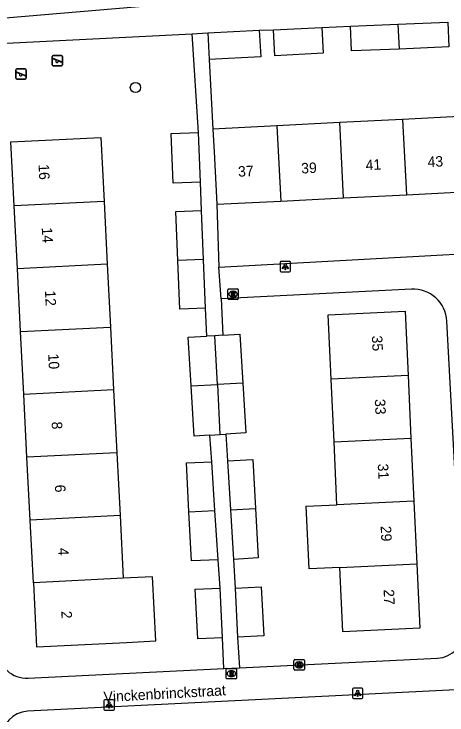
# Model space of a CAD drawing. Extents: x 160557 to 161245, y 385330 to 386505.
# Drawn here: x 160933.6 to 160974.9, y 385401.4 to 385468.3 of the extents above; entities that cross this region are included whole.
import ezdxf

# ---------------------------------------------------------------- set-up
doc = ezdxf.new("R2010")
doc.units = 0
for name, color, linetype in [('IMGEO_Boom', 7, 'Continuous'), ('IMGEO_Kolk', 7, 'Continuous'), ('IMGEO_Lichtpunt', 7, 'Continuous'), ('IMGEO_Openbare_ruimte_label', 7, 'Continuous'), ('IMGEO_Pand', 7, 'Continuous'), ('IMGEO_Pand_nummerreeks', 7, 'Continuous'), ('IMGEO_Rioolput', 7, 'Continuous'), ('IMGEO_Speelvoorziening', 7, 'Continuous'), ('IMGEO_Voetpad_open', 7, 'Continuous')]:
    doc.layers.add(name, color=color, linetype=linetype)

msp = doc.modelspace()

# ---------------------------------------------------------------- linework, layer by layer
at = {"layer": 'IMGEO_Boom'}
msp.add_circle((160945.22, 385461.28), 0.489, dxfattribs=at)
at = {"layer": 'IMGEO_Kolk'}
for p, q in [((160960.35, 385405.781), (160960.35, 385406.633)), ((160960.425, 385406.707), (160961.277, 385406.707)), ((160961.351, 385406.633), (160961.351, 385405.781)), ((160960.861, 385405.927), (160960.836, 385405.927)), ((160960.838, 385406.487), (160960.863, 385406.487)), ((160961.277, 385405.707), (160960.425, 385405.707))]:
    msp.add_line(p, q, dxfattribs=at)
for points in [[(160960.35, 385405.781), (160960.35, 385406.633)], [(160960.425, 385406.707), (160961.277, 385406.707)], [(160961.351, 385406.633), (160961.351, 385405.781)], [(160960.671, 385406.407), (160960.794, 385406.407), (160960.794, 385406.256), (160960.924, 385406.407), (160961.088, 385406.407), (160960.942, 385406.256), (160961.095, 385406.007), (160960.943, 385406.007), (160960.858, 385406.171), (160960.794, 385406.104), (160960.794, 385406.007), (160960.671, 385406.007), (160960.671, 385406.407)], [(160961.277, 385405.707), (160960.425, 385405.707)]]:
    msp.add_lwpolyline(points, dxfattribs=at)
for centre, start, end in [((160960.427, 385406.631), 91.55205, 178.44795), ((160960.427, 385406.631), 91.55205, 178.44795), ((160961.275, 385406.631), 1.55205, 88.44795), ((160961.275, 385406.631), 1.55205, 88.44795), ((160960.427, 385405.783), 181.55205, 268.44795), ((160960.427, 385405.783), 181.55205, 268.44795), ((160961.275, 385405.783), 271.55205, 358.44795), ((160961.275, 385405.783), 271.55205, 358.44795)]:
    msp.add_arc(centre, 0.0765, start, end, dxfattribs=at)
for centre, major_axis, ratio, start_param, end_param in [((160960.837, 385406.207), (-0.387, 0.002), 0.722429, 4.712389, 7.853982), ((160960.862, 385406.207), (-0.39, 0.002), 0.717154, 1.570796, 4.712389)]:
    msp.add_ellipse(centre, major_axis=major_axis, ratio=ratio, start_param=start_param, end_param=end_param, dxfattribs=at)
at = {"layer": 'IMGEO_Lichtpunt'}
for p, q in [((160959.925, 385444.698), (160959.117, 385444.698)), ((160959.925, 385444.698), (160959.117, 385444.698)), ((160959.023, 385444.603), (160959.023, 385443.796)), ((160959.023, 385444.603), (160959.023, 385443.796)), ((160960.019, 385443.796), (160960.019, 385444.603)), ((160960.019, 385443.796), (160960.019, 385444.603)), ((160959.117, 385443.702), (160959.925, 385443.702)), ((160959.117, 385443.702), (160959.925, 385443.702)), ((160965.922, 385403.892), (160965.922, 385403.085)), ((160965.922, 385403.892), (160965.922, 385403.085)), ((160966.824, 385403.987), (160966.016, 385403.987)), ((160966.824, 385403.987), (160966.016, 385403.987)), ((160966.918, 385403.085), (160966.918, 385403.892)), ((160966.918, 385403.085), (160966.918, 385403.892)), ((160942.224, 385402.782), (160942.224, 385401.975)), ((160942.224, 385402.782), (160942.224, 385401.975)), ((160943.126, 385402.877), (160942.318, 385402.877)), ((160943.126, 385402.877), (160942.318, 385402.877)), ((160943.22, 385401.975), (160943.22, 385402.782)), ((160943.22, 385401.975), (160943.22, 385402.782)), ((160966.016, 385402.991), (160966.824, 385402.991)), ((160966.016, 385402.991), (160966.824, 385402.991)), ((160942.318, 385401.881), (160943.126, 385401.881)), ((160942.318, 385401.881), (160943.126, 385401.881))]:
    msp.add_line(p, q, dxfattribs=at)
for points in [[(160959.397, 385444.267), (160959.436, 385444.239), (160959.248, 385443.977), (160959.21, 385444.004), (160959.397, 385444.267)], [(160959.499, 385444.219), (160959.546, 385444.219), (160959.546, 385443.897), (160959.499, 385443.897), (160959.499, 385444.219)], [(160959.609, 385444.239), (160959.647, 385444.266), (160959.834, 385444.004), (160959.795, 385443.976), (160959.609, 385444.239)], [(160966.296, 385403.556), (160966.335, 385403.528), (160966.147, 385403.266), (160966.109, 385403.293), (160966.296, 385403.556)], [(160966.398, 385403.508), (160966.445, 385403.508), (160966.445, 385403.186), (160966.398, 385403.186), (160966.398, 385403.508)], [(160966.508, 385403.528), (160966.546, 385403.555), (160966.733, 385403.293), (160966.694, 385403.265), (160966.508, 385403.528)], [(160942.598, 385402.446), (160942.637, 385402.418), (160942.449, 385402.156), (160942.411, 385402.183), (160942.598, 385402.446)], [(160942.7, 385402.398), (160942.747, 385402.398), (160942.747, 385402.076), (160942.7, 385402.076), (160942.7, 385402.398)], [(160942.81, 385402.418), (160942.848, 385402.445), (160943.035, 385402.183), (160942.996, 385402.155), (160942.81, 385402.418)]]:
    msp.add_lwpolyline(points, dxfattribs=at)
for centre in [(160959.522, 385444.401), (160966.421, 385403.69), (160942.723, 385402.58)]:
    msp.add_circle(centre, 0.0994, dxfattribs=at)
for centre, start, end in [((160959.117, 385444.603), 90, 180), ((160959.117, 385444.603), 90, 180), ((160959.925, 385444.603), 0, 90), ((160959.925, 385444.603), 0, 90), ((160959.117, 385443.796), 180, 270), ((160959.117, 385443.796), 180, 270), ((160959.925, 385443.796), 270, 0), ((160959.925, 385443.796), 270, 360), ((160966.016, 385403.892), 90, 180), ((160966.016, 385403.892), 90, 180), ((160966.824, 385403.892), 0, 90), ((160966.824, 385403.892), 0, 90), ((160942.318, 385402.782), 90, 180), ((160942.318, 385402.782), 90, 180), ((160943.126, 385402.782), 0, 90), ((160943.126, 385402.782), 0, 90), ((160966.016, 385403.085), 180, 270), ((160966.016, 385403.085), 180, 270), ((160966.824, 385403.085), 270, 0), ((160966.824, 385403.085), 270, 360), ((160942.318, 385401.975), 180, 270), ((160942.318, 385401.975), 180, 270), ((160943.126, 385401.975), 270, 0), ((160943.126, 385401.975), 270, 360)]:
    msp.add_arc(centre, 0.0946, start, end, dxfattribs=at)
at = {"layer": 'IMGEO_Pand'}
for points in [[(160970.249, 385467.317), (160975.025, 385467.513)], [(160975.025, 385467.513), (160975.122, 385465.147), (160970.369, 385464.952)], [(160952.133, 385466.483), (160957.037, 385466.746)], [(160957.037, 385466.746), (160957.172, 385464.2), (160952.27, 385463.937)], [(160958.396, 385466.774), (160962.99, 385467.01)], [(160962.99, 385467.01), (160963.117, 385464.544), (160958.523, 385464.308), (160958.396, 385466.774)], [(160965.726, 385467.131), (160970.249, 385467.317)], [(160970.369, 385464.952), (160965.823, 385464.765), (160965.726, 385467.131)], [(160970.249, 385467.317), (160970.369, 385464.952)], [(160952.133, 385466.483), (160952.27, 385463.937)], [(160970.707, 385458.23), (160964.715, 385457.926)], [(160976.7, 385458.533), (160970.707, 385458.23)], [(160970.707, 385458.23), (160971.071, 385451.053)], [(160958.723, 385457.623), (160952.612, 385457.313)], [(160964.715, 385457.926), (160958.723, 385457.623)], [(160958.723, 385457.623), (160959.087, 385450.446)], [(160965.079, 385450.749), (160964.715, 385457.926)], [(160951.427, 385452.25), (160948.811, 385452.143), (160948.617, 385456.879), (160951.233, 385456.986)], [(160951.427, 385452.25), (160951.233, 385456.986)], [(160952.612, 385457.313), (160952.723, 385455.13), (160952.976, 385450.136)], [(160933.656, 385449.978), (160933.345, 385456.087), (160941.918, 385456.524), (160942.229, 385450.415)], [(160971.071, 385451.053), (160977.064, 385451.357)], [(160959.087, 385450.446), (160965.079, 385450.749)], [(160965.079, 385450.749), (160971.071, 385451.053)], [(160942.229, 385450.415), (160933.656, 385449.978)], [(160933.961, 385443.986), (160933.656, 385449.978)], [(160942.229, 385450.415), (160942.534, 385444.423)], [(160952.976, 385450.136), (160959.087, 385450.446)], [(160949.275, 385444.764), (160949.082, 385449.441), (160951.536, 385449.542)], [(160951.727, 385444.889), (160951.536, 385449.542)], [(160951.727, 385444.889), (160949.275, 385444.764)], [(160951.919, 385440.23), (160949.466, 385440.129), (160949.275, 385444.764)], [(160951.919, 385440.23), (160951.727, 385444.889)], [(160942.534, 385444.423), (160933.961, 385443.986)], [(160934.266, 385437.994), (160933.961, 385443.986)], [(160942.534, 385444.423), (160942.839, 385438.431)], [(160963.892, 385433.471), (160963.607, 385439.608), (160970.947, 385439.948), (160971.232, 385433.812)], [(160934.266, 385437.994), (160942.839, 385438.431)], [(160934.571, 385432.002), (160934.266, 385437.994)], [(160942.839, 385438.431), (160943.144, 385432.439)], [(160950.527, 385432.815), (160950.246, 385437.45), (160952.033, 385437.559)], [(160952.802, 385437.606), (160952.033, 385437.559)], [(160953.565, 385437.652), (160952.802, 385437.606)], [(160953.037, 385432.943), (160952.802, 385437.606)], [(160953.565, 385437.652), (160955.187, 385437.75), (160955.471, 385433.067)], [(160971.232, 385433.812), (160963.892, 385433.471)], [(160964.17, 385427.478), (160963.892, 385433.471)], [(160971.232, 385433.812), (160971.51, 385427.819)], [(160950.527, 385432.815), (160953.037, 385432.943)], [(160952.336, 385428.118), (160950.818, 385428.026), (160950.527, 385432.815)], [(160955.471, 385433.067), (160953.037, 385432.943)], [(160953.037, 385432.943), (160953.277, 385428.175)], [(160955.471, 385433.067), (160955.759, 385428.326), (160953.852, 385428.21)], [(160943.144, 385432.439), (160934.571, 385432.002)], [(160934.876, 385426.009), (160934.571, 385432.002)], [(160943.144, 385432.439), (160943.449, 385426.446)], [(160952.336, 385428.118), (160953.277, 385428.175)], [(160953.277, 385428.175), (160953.852, 385428.21)], [(160964.17, 385427.478), (160971.51, 385427.819)], [(160964.448, 385421.484), (160964.17, 385427.478)], [(160971.51, 385427.819), (160971.788, 385421.825)], [(160943.449, 385426.446), (160934.876, 385426.009)], [(160935.181, 385420.017), (160934.876, 385426.009)], [(160943.449, 385426.446), (160943.754, 385420.454)], [(160950.33, 385420.792), (160950.082, 385425.468), (160952.504, 385425.573)], [(160952.811, 385420.918), (160952.504, 385425.573)], [(160954.008, 385425.668), (160956.424, 385425.789), (160956.677, 385421.12)], [(160954.008, 385425.668), (160954.293, 385421.009)], [(160964.725, 385415.49), (160961.79, 385415.354), (160961.512, 385421.348), (160964.448, 385421.484)], [(160971.788, 385421.825), (160964.448, 385421.484)], [(160971.788, 385421.825), (160972.066, 385415.831)], [(160950.33, 385420.792), (160952.811, 385420.918)], [(160953.12, 385416.234), (160950.578, 385416.133), (160950.33, 385420.792)], [(160953.12, 385416.234), (160952.811, 385420.918)], [(160954.293, 385421.009), (160956.677, 385421.12)], [(160954.293, 385421.009), (160954.584, 385416.261)], [(160956.677, 385421.12), (160956.933, 385416.403), (160954.584, 385416.261)], [(160943.754, 385420.454), (160935.181, 385420.017)], [(160935.486, 385414.025), (160935.181, 385420.017)], [(160943.754, 385420.454), (160944.059, 385414.462)], [(160972.066, 385415.831), (160972.351, 385409.695), (160965.01, 385409.355), (160964.725, 385415.49)], [(160964.725, 385415.49), (160972.066, 385415.831)], [(160935.486, 385414.025), (160935.797, 385407.918), (160944.37, 385408.354), (160947.157, 385408.496), (160946.846, 385414.604), (160944.059, 385414.462)], [(160944.059, 385414.462), (160935.486, 385414.025)], [(160953.526, 385408.799), (160951.164, 385408.685), (160950.936, 385413.419), (160953.298, 385413.533)], [(160953.526, 385408.799), (160953.298, 385413.533)], [(160954.752, 385413.517), (160957.233, 385413.637), (160957.457, 385408.98), (160954.976, 385408.86)], [(160954.752, 385413.517), (160954.976, 385408.86)]]:
    msp.add_lwpolyline(points, dxfattribs=at)
at = {"layer": 'IMGEO_Rioolput'}
for p, q in [((160954.035, 385441.14), (160954.035, 385441.992)), ((160954.11, 385442.066), (160954.962, 385442.066)), ((160955.036, 385441.992), (160955.036, 385441.14)), ((160954.546, 385441.286), (160954.521, 385441.286)), ((160954.523, 385441.846), (160954.548, 385441.846)), ((160954.962, 385441.066), (160954.11, 385441.066)), ((160953.952, 385405.872), (160954.804, 385405.872)), ((160953.877, 385404.946), (160953.877, 385405.798)), ((160954.365, 385405.652), (160954.39, 385405.652)), ((160954.878, 385405.798), (160954.878, 385404.946)), ((160954.804, 385404.872), (160953.952, 385404.872)), ((160954.388, 385405.092), (160954.363, 385405.092))]:
    msp.add_line(p, q, dxfattribs=at)
for points in [[(160954.035, 385441.14), (160954.035, 385441.992)], [(160954.11, 385442.066), (160954.962, 385442.066)], [(160955.036, 385441.992), (160955.036, 385441.14)], [(160954.624, 385441.764), (160954.372, 385441.766), (160954.372, 385441.366)], [(160954.372, 385441.366), (160954.496, 385441.366), (160954.496, 385441.528), (160954.507, 385441.528)], [(160954.55, 385441.685), (160954.496, 385441.685), (160954.496, 385441.604)], [(160954.496, 385441.604), (160954.548, 385441.604)], [(160954.554, 385441.499), (160954.625, 385441.366), (160954.765, 385441.366), (160954.7, 385441.492)], [(160954.962, 385441.066), (160954.11, 385441.066)], [(160953.952, 385405.872), (160954.804, 385405.872)], [(160953.877, 385404.946), (160953.877, 385405.798)], [(160954.466, 385405.57), (160954.214, 385405.572), (160954.214, 385405.172)], [(160954.214, 385405.172), (160954.338, 385405.172), (160954.338, 385405.334), (160954.349, 385405.334)], [(160954.392, 385405.491), (160954.338, 385405.491), (160954.338, 385405.41)], [(160954.338, 385405.41), (160954.39, 385405.41)], [(160954.396, 385405.305), (160954.467, 385405.172), (160954.607, 385405.172), (160954.542, 385405.298)], [(160954.878, 385405.798), (160954.878, 385404.946)], [(160954.804, 385404.872), (160953.952, 385404.872)]]:
    msp.add_lwpolyline(points, dxfattribs=at)
for centre, radius, start, end in [((160954.112, 385441.99), 0.0765, 91.55205, 178.44795), ((160954.112, 385441.99), 0.0765, 91.55205, 178.44795), ((160954.96, 385441.99), 0.0765, 1.55205, 88.44795), ((160954.96, 385441.99), 0.0765, 1.55205, 88.44795), ((160954.506, 385441.475), 0.0533, 26.02933, 88.69889), ((160954.532, 385441.793), 0.19, 274.7715, 282.96867), ((160954.556, 385441.589), 0.0964, 77.00612, 93.18647), ((160954.57, 385441.646), 0.0378, 276.66336, 79.67722), ((160954.623, 385441.654), 0.109, 350.36119, 89.41601), ((160954.621, 385441.654), 0.112, 277.58423, 350.98172), ((160954.605, 385441.439), 0.108, 29.51342, 73.79051), ((160954.112, 385441.142), 0.0765, 181.55205, 268.44795), ((160954.112, 385441.142), 0.0765, 181.55205, 268.44795), ((160954.96, 385441.142), 0.0765, 271.55205, 358.44795), ((160954.96, 385441.142), 0.0765, 271.55205, 358.44795), ((160953.954, 385405.796), 0.0765, 91.55205, 178.44795), ((160953.954, 385405.796), 0.0765, 91.55205, 178.44795), ((160954.802, 385405.796), 0.0765, 1.55205, 88.44795), ((160954.802, 385405.796), 0.0765, 1.55205, 88.44795), ((160954.348, 385405.281), 0.0533, 26.02933, 88.69889), ((160954.374, 385405.599), 0.19, 274.7715, 282.96867), ((160954.398, 385405.395), 0.0964, 77.00612, 93.18647), ((160954.412, 385405.452), 0.0378, 276.66336, 79.67722), ((160954.465, 385405.46), 0.109, 350.36119, 89.41601), ((160954.463, 385405.46), 0.112, 277.58423, 350.98172), ((160954.447, 385405.245), 0.108, 29.51342, 73.79051), ((160953.954, 385404.948), 0.0765, 181.55205, 268.44795), ((160953.954, 385404.948), 0.0765, 181.55205, 268.44795), ((160954.802, 385404.948), 0.0765, 271.55205, 358.44795), ((160954.802, 385404.948), 0.0765, 271.55205, 358.44795)]:
    msp.add_arc(centre, radius, start, end, dxfattribs=at)
for centre, major_axis, ratio, start_param, end_param in [((160954.522, 385441.566), (-0.387, 0.002), 0.722429, 4.712389, 7.853982), ((160954.547, 385441.566), (-0.39, 0.002), 0.717154, 1.570796, 4.712389), ((160954.364, 385405.372), (-0.387, 0.002), 0.722429, 4.712389, 7.853982), ((160954.389, 385405.372), (-0.39, 0.002), 0.717154, 1.570796, 4.712389)]:
    msp.add_ellipse(centre, major_axis=major_axis, ratio=ratio, start_param=start_param, end_param=end_param, dxfattribs=at)
at = {"layer": 'IMGEO_Speelvoorziening'}
for p, q in [((160937.284, 385463.444), (160937.284, 385464.244)), ((160937.284, 385464.244), (160937.284, 385463.444)), ((160937.353, 385464.069), (160938.229, 385463.716)), ((160937.384, 385464.344), (160938.174, 385464.344)), ((160938.174, 385464.344), (160937.384, 385464.344)), ((160938.274, 385464.244), (160938.274, 385463.444)), ((160938.274, 385463.444), (160938.274, 385464.244)), ((160937.667, 385463.872), (160937.328, 385464.009)), ((160938.205, 385463.656), (160937.865, 385463.793)), ((160933.817, 385462.162), (160933.817, 385462.962)), ((160933.817, 385462.962), (160933.817, 385462.162)), ((160934.2, 385462.59), (160933.861, 385462.727)), ((160933.886, 385462.787), (160934.762, 385462.434)), ((160933.917, 385463.062), (160934.707, 385463.062)), ((160934.707, 385463.062), (160933.917, 385463.062)), ((160934.807, 385462.962), (160934.807, 385462.162)), ((160934.807, 385462.162), (160934.807, 385462.962)), ((160938.174, 385463.344), (160937.384, 385463.344)), ((160937.384, 385463.344), (160938.174, 385463.344)), ((160934.707, 385462.062), (160933.917, 385462.062)), ((160933.917, 385462.062), (160934.707, 385462.062)), ((160934.738, 385462.374), (160934.398, 385462.511))]:
    msp.add_line(p, q, dxfattribs=at)
for centre, radius, start, end in [((160937.384, 385464.244), 0.1, 90, 180), ((160937.384, 385464.244), 0.1, 90, 180), ((160937.341, 385464.039), 0.0327, 68.07798, 248.07798), ((160938.174, 385464.244), 0.1, 0, 90), ((160938.174, 385464.244), 0.1, 360, 90), ((160937.384, 385463.444), 0.1, 180, 270), ((160937.384, 385463.444), 0.1, 180, 270), ((160937.746, 385463.782), 0.12, 130.99278, 5.16318), ((160938.174, 385463.444), 0.1, 270, 0), ((160938.174, 385463.444), 0.1, 270, 0), ((160938.217, 385463.686), 0.0327, 248.07798, 68.07798), ((160933.917, 385462.962), 0.1, 90, 180), ((160933.917, 385462.962), 0.1, 90, 180), ((160933.874, 385462.757), 0.0327, 68.07798, 248.07798), ((160934.707, 385462.962), 0.1, 0, 90), ((160934.707, 385462.962), 0.1, 360, 90), ((160933.917, 385462.162), 0.1, 180, 270), ((160933.917, 385462.162), 0.1, 180, 270), ((160934.279, 385462.5), 0.12, 130.99278, 5.16318), ((160934.707, 385462.162), 0.1, 270, 0), ((160934.707, 385462.162), 0.1, 270, 0), ((160934.75, 385462.404), 0.0327, 248.07798, 68.07798)]:
    msp.add_arc(centre, radius, start, end, dxfattribs=at)
at = {"layer": 'IMGEO_Voetpad_open'}
for points in [[(160951.932, 385469.506), (160926.05, 385467.331)], [(160957.037, 385466.746), (160958.396, 385466.774)], [(160962.99, 385467.01), (160965.726, 385467.131)], [(160929.105, 385465.306), (160950.644, 385466.407)], [(160950.644, 385466.407), (160952.133, 385466.483)], [(160951.233, 385456.986), (160950.644, 385466.407)], [(160952.27, 385463.937), (160952.612, 385457.313)], [(160951.536, 385449.542), (160951.427, 385452.25)], [(160952.976, 385450.136), (160953.174, 385444.144)], [(160953.174, 385444.144), (161000, 385446.726)], [(160953.418, 385441.133), (160953.174, 385444.144)], [(160971.544, 385442.046), (160953.418, 385441.133)], [(160953.418, 385441.133), (160953.565, 385437.652)], [(160952.033, 385437.559), (160951.919, 385440.23)], [(160976.517, 385409.594), (160974.944, 385438.982)], [(160952.504, 385425.573), (160952.336, 385428.118)], [(160953.852, 385428.21), (160954.008, 385425.668)], [(160953.298, 385413.533), (160953.12, 385416.234)], [(160954.584, 385416.261), (160954.752, 385413.517)], [(160953.662, 385405.847), (160953.526, 385408.799)], [(160954.976, 385408.86), (160955.142, 385405.919)], [(160955.142, 385405.919), (160974.031, 385406.842)], [(160934.999, 385404.935), (160953.662, 385405.847)], [(160953.662, 385405.847), (160955.142, 385405.919)], [(160991.765, 385404.634), (160934.942, 385401.788)]]:
    msp.add_lwpolyline(points, dxfattribs=at)
for centre, radius, start, end in [((160971.708, 385438.809), 3.241, 3.05759, 92.89355), ((160973.905, 385409.454), 2.615, 272.75189, 3.06239), ((160934.862, 385407.74), 2.808, 182.9374, 272.80475), ((160935.091, 385399.162), 2.631, 93.25757, 181.60633)]:
    msp.add_arc(centre, radius, start, end, dxfattribs=at)

# ---------------------------------------------------------------- texts
at = {"layer": 'IMGEO_Openbare_ruimte_label'}
msp.add_text('Vinckenbrinckstraat', height=1, rotation=3.26885, dxfattribs=at).set_placement((160942.213, 385402.643))
at = {"layer": 'IMGEO_Pand_nummerreeks'}
for s, rotation, p in [('43', 2.90129, (160973.116, 385453.68)), ('39', 2.90129, (160961.063, 385453.069)), ('41', 2.90129, (160967.203, 385453.38)), ('16', 272.91407, (160935.978, 385453.939)), ('37', 2.90129, (160955.037, 385452.764)), ('14', 272.91407, (160936.284, 385447.918)), ('12', 272.91407, (160936.591, 385441.9)), ('35', 272.65711, (160967.773, 385437.596)), ('10', 272.91407, (160936.897, 385435.872)), ('33', 272.65711, (160968.053, 385431.546)), ('8', 272.91407, (160937.227, 385429.39)), ('31', 272.65711, (160968.339, 385425.382)), ('6', 272.91407, (160937.533, 385423.373)), ('29', 272.65831, (160968.616, 385419.444)), ('4', 272.91407, (160937.84, 385417.352)), ('27', 272.65711, (160968.896, 385413.394)), ('2', 272.91614, (160938.147, 385411.333))]:
    msp.add_text(s, height=1, rotation=rotation, dxfattribs=at).set_placement(p)

doc.saveas('drawing.dxf')
